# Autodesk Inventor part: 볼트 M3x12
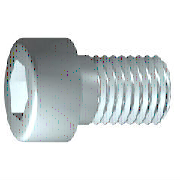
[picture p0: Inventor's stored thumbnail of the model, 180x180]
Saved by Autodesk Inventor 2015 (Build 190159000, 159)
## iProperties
IsCustomPart: 0
Created: 2012-02
Part Number: 볼트 M3x12
Material: 강철, 연강
Description: 6각머리 태핑 나사
Document SubType Name: Modeling
Standard: KS B 1003
Designer: mduedu
Standards Organization: KS
Language: ko-KR
Size Designation: M 3 x 12
Categories: <MemberInstance><Categories><Category DisplayName="조임쇠" InternalName="e4da775c-781d-43d5-af7c-5136215cf5a6" Mnemonic="FSTN"><Category DisplayName="볼트" InternalN
Density: 7.85 g/cm^3
Appearance: 강철
Mass: 1.15061 g
Surface Area: 2.207 cm^2
Volume: 0.146575 cm^3
Author: mduedu
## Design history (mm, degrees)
sketch "스케치1"
  geometry: L1 (-0.867, 0)-(12, 0); L2 (12, 0)-(12, 1.5); L3 (12, 1.5)-(1.25, 1.5); L4 (1.25, 1.5)-(0.943, 1.5); L5 (0.943, 1.5)-(0, 1.5); L6 (0, 1.5)-(0, 2.75); L7 (0, 2.75)-(-3, 2.75); L8 (-3, 2.75)-(-3, 1.443); L9 (-3, 1.443)-(-1.7, 1.443); L10 (-1.7, 1.443)-(-0.867, 0); L11 (-6, 0)-(15, 0) reference; L12 (0, -0.55)-(0, 3.3) reference; L13 (1.25, 1.5)-(0, 1.5)
  constraints: 22 end point, 6 parallel, 2 collinear, 2 perpendicular, 1 horizontal, 1 point on line
  dimensions: "d1" = 10.75 distance from line of L3.end L2 (= GEL); "d2" = 0.30683 distance of L4.end L3.end (computed from GAL); "d3" = 3 distance between parallel lines of L8 L6 (= KOH); "d4" = 1.3 distance of L8.end L9.end (= INTI); "d5" = 60 deg angle of L10 L1; "d6" = 3 diameter of L3 L1 (= GD); "d7" = 3 diameter of L5 L1 (= BDM); "d8" = 2.88675 diameter of L9 L1 (= 1.1547 x SW); "d9" = 5.5 diameter of L7 L1 (= KOD); "d26" = 12 distance between parallel lines of L12 L2 (= NLG)
revolve "본체" sketch "스케치1" stored, may be unused: angle "d10" = 90 deg
sketch "스케치2"
  geometry: L1 (0, -3.85)-(0, 3.85) reference; L2 (-3.85, 0)-(3.85, 0) reference; L3 (1.443, 0)-(0.722, -1.25); L4 (0.722, -1.25)-(-0.722, -1.25); L5 (-0.722, -1.25)-(-1.443, 0); L6 (-1.443, 0)-(-0.722, 1.25); L7 (-0.722, 1.25)-(0.722, 1.25); L8 (0.722, 1.25)-(1.443, 0); 2 further points
  constraints: 12 end point, 1 coincident, 1 horizontal alignment, 1 point on line, 12 other
extrude "슬롯" join sketch "스케치2" stored distance "d11" = 10; taper "d12" = 0 deg
workplane "Work Plane1"
fillet "Fillet2" dims "d30" = 0.1 (= R)
body "Solid1"
fillet "모깎기1" dims "d17" = 0.3 (= RR)
feature "스레드" dims "d13" = 10.75 (= GEL), "d14" = 0
chamfer "모따기1" distance "d15" = 0.30673 (= -0.5 x SPD + 0.5 x GD); stored, may be unused: second distance "d16" = 0.30673 (= GUL), angle "d27" = 45 deg
other parameters: "GD" = 3 (= NND) [user parameter; used in 2 equation terms], "NLG" = 12 [user parameter; used in 1 equation term], "GEL" = 10.75 [user parameter; used in 2 equation terms], "KOD" = 5.5 [user parameter; used in 1 equation term], "KOH" = 3 [user parameter; used in 1 equation term], "INTI" = 1.3 [user parameter; used in 1 equation term], "GAL" = 0.30673 (= 0.61345 x PTC) [user parameter; used in 1 equation term], "GUL" = 0.30673 (= 0.61345 x PTC) [user parameter; used in 1 equation term], "BDM" = 3 (= NND) [user parameter; used in 1 equation term], "SW" = 2.5 [user parameter; used in 2 equation terms], "RR" = 0.3 [user parameter; used in 1 equation term], "SPD" = 2.38655 (= NND - 1.2269 x PTC) [user parameter; used in 1 equation term], "d19" = 0, "d28" = 0, "d29" = 0, "R" = 0.1 [user parameter; used in 1 equation term], "PHH" = 0.1 [user parameter], "GD1" = 2.38655 (= THREADDIA - 1.2269 x PTC) [user parameter], "THREADDIA" = 3 [user parameter; used in 1 equation term], "FAWI" = 45 deg [user parameter], "PTC" = 0.5 [user parameter; used in 5 equation terms], "NND" = 3 [user parameter; used in 3 equation terms], "TOA" = 30 deg [user parameter], "E0" = 2.8875 (= 1.155 x SW) [user parameter]
